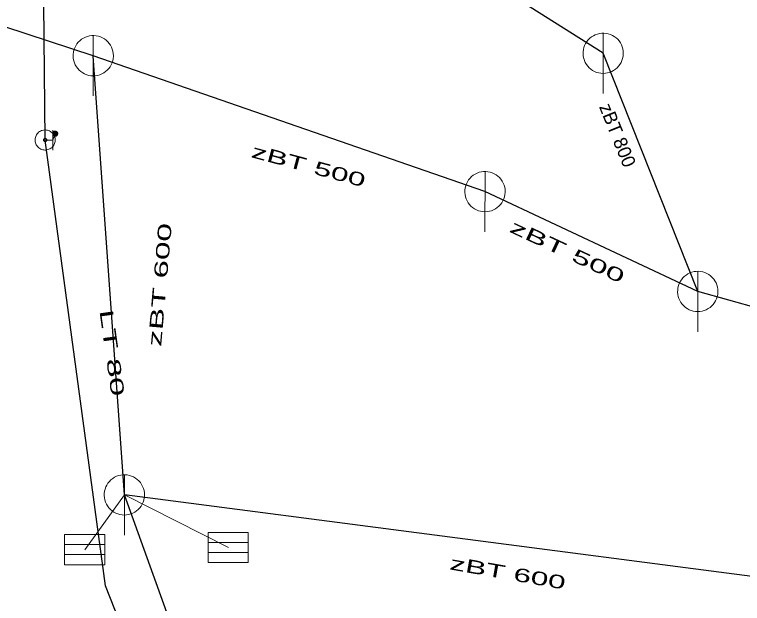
# Model space of a CAD drawing. Extents: x -688432 to -687974, y -973332 to -972704.
# Drawn here: x -688250.99 to -688214.87, y -972905.19 to -972875.96 of the extents above; entities that cross this region are included whole.
import ezdxf
from ezdxf.enums import TextEntityAlignment as Align

# ---------------------------------------------------------------- set-up
doc = ezdxf.new("R2010")
doc.units = 0
doc.header["$LTSCALE"] = 0.27
for name, color, linetype, lineweight in [('1', 7, 'Continuous', 25), ('11', 7, 'Continuous', 13), ('14', 7, 'Continuous', 25), ('17', 7, 'Continuous', 25), ('22', 7, 'Continuous', 13), ('34', 7, 'Continuous', 13), ('47', 7, 'Continuous', 13), ('9', 7, 'Continuous', 13)]:
    doc.layers.add(name, color=color, linetype=linetype, lineweight=lineweight)

msp = doc.modelspace()

# ---------------------------------------------------------------- linework, layer by layer
at = {"layer": '11'}
for p in [(-688247.495, -972902.523), (-688240.377, -972902.418)]:
    msp.add_line(p, (-688245.539, -972899.801), dxfattribs=at)
at = {"layer": '14'}
for p, q in [((-688221.777, -972877.88), (-688271.103, -972846.579)), ((-688217.084, -972889.702), (-688221.777, -972877.88)), ((-688245.539, -972899.801), (-688247.084, -972877.999)), ((-688175.649, -972901.305), (-688217.084, -972889.702)), ((-688238.57, -972919.1), (-688245.539, -972899.801)), ((-688206.6, -972904.874), (-688245.539, -972899.801))]:
    msp.add_line(p, q, dxfattribs=at)
msp.add_lwpolyline([(-688217.084, -972889.702), (-688227.642, -972884.745), (-688247.084, -972877.999), (-688290.938, -972863.596)], dxfattribs=at)
at = {"layer": '14', "lineweight": 13}
msp.add_lwpolyline([(-688249.47, -972882.184), (-688249.091, -972882.189), (-688248.971, -972881.872)], dxfattribs=at)
at = {"layer": '17'}
for points in [[(-688249.47, -972882.184), (-688249.846, -972843.218), (-688249.92, -972842.489), (-688249.989, -972841.809), (-688250.385, -972837.918)], [(-688239.23, -972922.68), (-688246.472, -972904.316), (-688249.47, -972882.184)]]:
    msp.add_lwpolyline(points, dxfattribs=at)
at = {"layer": '22'}
for p, q in [((-688247.084, -972879.999), (-688247.083, -972876.999)), ((-688221.777, -972879.88), (-688221.776, -972876.88)), ((-688227.642, -972886.746), (-688227.641, -972883.746)), ((-688217.084, -972891.702), (-688217.083, -972888.702)), ((-688245.539, -972901.801), (-688245.538, -972898.801)), ((-688248.506, -972902.266), (-688246.506, -972902.266)), ((-688241.388, -972902.161), (-688239.388, -972902.161)), ((-688248.506, -972902.766), (-688246.506, -972902.766)), ((-688241.388, -972902.661), (-688239.388, -972902.661))]:
    msp.add_line(p, q, dxfattribs=at)
for points in [[(-688246.084, -972877.999), (-688246.089, -972877.89), (-688246.107, -972877.782), (-688246.137, -972877.676), (-688246.177, -972877.575), (-688246.229, -972877.478), (-688246.291, -972877.388), (-688246.363, -972877.305), (-688246.443, -972877.231), (-688246.531, -972877.165), (-688246.625, -972877.11), (-688246.725, -972877.065), (-688246.83, -972877.032), (-688246.937, -972877.01), (-688247.046, -972877), (-688247.156, -972877.002), (-688247.264, -972877.016), (-688247.371, -972877.041), (-688247.474, -972877.078), (-688247.572, -972877.127), (-688247.664, -972877.185), (-688247.75, -972877.254), (-688247.827, -972877.331), (-688247.896, -972877.417), (-688247.955, -972877.509), (-688248.003, -972877.607), (-688248.04, -972877.71), (-688248.066, -972877.817), (-688248.08, -972877.925), (-688248.083, -972878.035), (-688248.073, -972878.144), (-688248.052, -972878.251), (-688248.018, -972878.355), (-688247.974, -972878.455), (-688247.919, -972878.55), (-688247.853, -972878.638), (-688247.779, -972878.718), (-688247.696, -972878.79), (-688247.606, -972878.852), (-688247.51, -972878.904), (-688247.408, -972878.945), (-688247.303, -972878.975), (-688247.195, -972878.993), (-688247.085, -972878.999), (-688246.976, -972878.993), (-688246.868, -972878.975), (-688246.763, -972878.946), (-688246.661, -972878.905), (-688246.564, -972878.853), (-688246.474, -972878.791), (-688246.391, -972878.72), (-688246.316, -972878.64), (-688246.251, -972878.552), (-688246.195, -972878.458), (-688246.151, -972878.358), (-688246.117, -972878.254), (-688246.095, -972878.146), (-688246.085, -972878.037)], [(-688220.777, -972877.88), (-688220.782, -972877.771), (-688220.8, -972877.663), (-688220.83, -972877.557), (-688220.87, -972877.456), (-688220.922, -972877.359), (-688220.984, -972877.269), (-688221.056, -972877.186), (-688221.136, -972877.112), (-688221.224, -972877.046), (-688221.318, -972876.991), (-688221.418, -972876.946), (-688221.523, -972876.913), (-688221.63, -972876.891), (-688221.739, -972876.881), (-688221.849, -972876.883), (-688221.957, -972876.897), (-688222.064, -972876.922), (-688222.167, -972876.959), (-688222.265, -972877.008), (-688222.357, -972877.066), (-688222.443, -972877.135), (-688222.52, -972877.212), (-688222.589, -972877.298), (-688222.648, -972877.39), (-688222.696, -972877.488), (-688222.733, -972877.591), (-688222.759, -972877.698), (-688222.773, -972877.806), (-688222.776, -972877.916), (-688222.766, -972878.025), (-688222.745, -972878.132), (-688222.711, -972878.236), (-688222.667, -972878.336), (-688222.612, -972878.431), (-688222.546, -972878.519), (-688222.472, -972878.599), (-688222.389, -972878.671), (-688222.299, -972878.733), (-688222.203, -972878.785), (-688222.101, -972878.826), (-688221.996, -972878.856), (-688221.888, -972878.874), (-688221.778, -972878.88), (-688221.669, -972878.874), (-688221.561, -972878.856), (-688221.456, -972878.827), (-688221.354, -972878.786), (-688221.257, -972878.734), (-688221.167, -972878.672), (-688221.084, -972878.601), (-688221.009, -972878.521), (-688220.944, -972878.433), (-688220.888, -972878.339), (-688220.844, -972878.239), (-688220.81, -972878.135), (-688220.788, -972878.027), (-688220.778, -972877.918)], [(-688226.642, -972884.746), (-688226.647, -972884.637), (-688226.665, -972884.529), (-688226.695, -972884.423), (-688226.735, -972884.322), (-688226.787, -972884.225), (-688226.849, -972884.135), (-688226.921, -972884.052), (-688227.001, -972883.978), (-688227.089, -972883.912), (-688227.183, -972883.857), (-688227.283, -972883.812), (-688227.388, -972883.779), (-688227.495, -972883.757), (-688227.604, -972883.747), (-688227.714, -972883.749), (-688227.822, -972883.763), (-688227.929, -972883.788), (-688228.032, -972883.825), (-688228.13, -972883.874), (-688228.222, -972883.932), (-688228.308, -972884.001), (-688228.385, -972884.078), (-688228.454, -972884.164), (-688228.513, -972884.256), (-688228.561, -972884.354), (-688228.598, -972884.457), (-688228.624, -972884.564), (-688228.638, -972884.672), (-688228.641, -972884.782), (-688228.631, -972884.891), (-688228.61, -972884.998), (-688228.576, -972885.102), (-688228.532, -972885.202), (-688228.477, -972885.297), (-688228.411, -972885.385), (-688228.337, -972885.465), (-688228.254, -972885.537), (-688228.164, -972885.599), (-688228.068, -972885.651), (-688227.966, -972885.692), (-688227.861, -972885.722), (-688227.753, -972885.74), (-688227.643, -972885.746), (-688227.534, -972885.74), (-688227.426, -972885.722), (-688227.321, -972885.693), (-688227.219, -972885.652), (-688227.122, -972885.6), (-688227.032, -972885.538), (-688226.949, -972885.467), (-688226.874, -972885.387), (-688226.809, -972885.299), (-688226.753, -972885.205), (-688226.709, -972885.105), (-688226.675, -972885.001), (-688226.653, -972884.893), (-688226.643, -972884.784)], [(-688216.084, -972889.702), (-688216.089, -972889.593), (-688216.107, -972889.485), (-688216.137, -972889.379), (-688216.177, -972889.278), (-688216.229, -972889.181), (-688216.291, -972889.091), (-688216.363, -972889.008), (-688216.443, -972888.934), (-688216.531, -972888.868), (-688216.625, -972888.813), (-688216.725, -972888.768), (-688216.83, -972888.735), (-688216.937, -972888.713), (-688217.046, -972888.703), (-688217.156, -972888.705), (-688217.264, -972888.719), (-688217.371, -972888.744), (-688217.474, -972888.781), (-688217.572, -972888.83), (-688217.664, -972888.888), (-688217.75, -972888.957), (-688217.827, -972889.034), (-688217.896, -972889.12), (-688217.955, -972889.212), (-688218.003, -972889.31), (-688218.04, -972889.413), (-688218.066, -972889.52), (-688218.08, -972889.628), (-688218.083, -972889.738), (-688218.073, -972889.847), (-688218.052, -972889.954), (-688218.018, -972890.058), (-688217.974, -972890.158), (-688217.919, -972890.253), (-688217.853, -972890.341), (-688217.779, -972890.421), (-688217.696, -972890.493), (-688217.606, -972890.555), (-688217.51, -972890.607), (-688217.408, -972890.648), (-688217.303, -972890.678), (-688217.195, -972890.696), (-688217.085, -972890.702), (-688216.976, -972890.696), (-688216.868, -972890.678), (-688216.763, -972890.649), (-688216.661, -972890.608), (-688216.564, -972890.556), (-688216.474, -972890.494), (-688216.391, -972890.423), (-688216.316, -972890.343), (-688216.251, -972890.255), (-688216.195, -972890.161), (-688216.151, -972890.061), (-688216.117, -972889.957), (-688216.095, -972889.849), (-688216.085, -972889.74)], [(-688244.539, -972899.801), (-688244.544, -972899.692), (-688244.562, -972899.584), (-688244.592, -972899.478), (-688244.632, -972899.377), (-688244.684, -972899.28), (-688244.746, -972899.19), (-688244.818, -972899.107), (-688244.898, -972899.033), (-688244.986, -972898.967), (-688245.08, -972898.912), (-688245.18, -972898.867), (-688245.285, -972898.834), (-688245.392, -972898.812), (-688245.501, -972898.802), (-688245.611, -972898.804), (-688245.719, -972898.818), (-688245.826, -972898.843), (-688245.929, -972898.88), (-688246.027, -972898.929), (-688246.119, -972898.987), (-688246.205, -972899.056), (-688246.282, -972899.133), (-688246.351, -972899.219), (-688246.41, -972899.311), (-688246.458, -972899.409), (-688246.495, -972899.512), (-688246.521, -972899.619), (-688246.535, -972899.727), (-688246.538, -972899.837), (-688246.528, -972899.946), (-688246.507, -972900.053), (-688246.473, -972900.157), (-688246.429, -972900.257), (-688246.374, -972900.352), (-688246.308, -972900.44), (-688246.234, -972900.52), (-688246.151, -972900.592), (-688246.061, -972900.654), (-688245.965, -972900.706), (-688245.863, -972900.747), (-688245.758, -972900.777), (-688245.65, -972900.795), (-688245.54, -972900.801), (-688245.431, -972900.795), (-688245.323, -972900.777), (-688245.218, -972900.748), (-688245.116, -972900.707), (-688245.019, -972900.655), (-688244.929, -972900.593), (-688244.846, -972900.522), (-688244.771, -972900.442), (-688244.706, -972900.354), (-688244.65, -972900.26), (-688244.606, -972900.16), (-688244.572, -972900.056), (-688244.55, -972899.948), (-688244.54, -972899.839)], [(-688248.506, -972901.766), (-688246.506, -972901.766), (-688246.506, -972903.266), (-688248.506, -972903.266)], [(-688241.388, -972901.661), (-688239.388, -972901.661), (-688239.388, -972903.161), (-688241.388, -972903.161)]]:
    msp.add_lwpolyline(points, close=True, dxfattribs=at)
at = {"layer": '34'}
msp.add_line((-688249.091, -972881.689), (-688249.091, -972882.689), dxfattribs=at)
at = {"layer": '47'}
for points in [[(-688249.432, -972882.682), (-688249.381, -972882.675), (-688249.329, -972882.663), (-688249.281, -972882.646), (-688249.233, -972882.624), (-688249.188, -972882.597), (-688249.146, -972882.565), (-688249.109, -972882.529), (-688249.075, -972882.489), (-688249.045, -972882.447), (-688249.019, -972882.401), (-688248.999, -972882.352), (-688248.984, -972882.302), (-688248.974, -972882.251), (-688248.97, -972882.198), (-688248.971, -972882.146), (-688248.978, -972882.095), (-688248.99, -972882.043), (-688249.007, -972881.994), (-688249.029, -972881.947), (-688249.056, -972881.902), (-688249.088, -972881.86), (-688249.124, -972881.822), (-688249.164, -972881.788), (-688249.206, -972881.758), (-688249.252, -972881.733), (-688249.301, -972881.713), (-688249.351, -972881.697), (-688249.402, -972881.688), (-688249.455, -972881.684), (-688249.507, -972881.685), (-688249.558, -972881.692), (-688249.61, -972881.704), (-688249.659, -972881.72), (-688249.706, -972881.743), (-688249.751, -972881.77), (-688249.793, -972881.801), (-688249.831, -972881.837), (-688249.865, -972881.877), (-688249.895, -972881.92), (-688249.92, -972881.966), (-688249.94, -972882.015), (-688249.956, -972882.064), (-688249.965, -972882.116), (-688249.969, -972882.169), (-688249.968, -972882.221), (-688249.961, -972882.272), (-688249.949, -972882.324), (-688249.933, -972882.372), (-688249.91, -972882.42), (-688249.883, -972882.465), (-688249.852, -972882.507), (-688249.816, -972882.544), (-688249.776, -972882.578), (-688249.733, -972882.608), (-688249.687, -972882.634), (-688249.638, -972882.654), (-688249.589, -972882.669), (-688249.537, -972882.679), (-688249.484, -972882.683)], [(-688249.463, -972882.265), (-688249.454, -972882.265), (-688249.447, -972882.262), (-688249.439, -972882.259), (-688249.431, -972882.256), (-688249.423, -972882.251), (-688249.417, -972882.246), (-688249.41, -972882.24), (-688249.405, -972882.234), (-688249.4, -972882.226), (-688249.396, -972882.219), (-688249.392, -972882.211), (-688249.39, -972882.203), (-688249.388, -972882.195), (-688249.387, -972882.186), (-688249.388, -972882.177), (-688249.388, -972882.168), (-688249.391, -972882.161), (-688249.394, -972882.153), (-688249.397, -972882.145), (-688249.402, -972882.137), (-688249.407, -972882.131), (-688249.413, -972882.124), (-688249.419, -972882.119), (-688249.427, -972882.113), (-688249.434, -972882.11), (-688249.442, -972882.106), (-688249.45, -972882.104), (-688249.458, -972882.102), (-688249.467, -972882.101), (-688249.476, -972882.102), (-688249.485, -972882.102), (-688249.492, -972882.105), (-688249.5, -972882.108), (-688249.508, -972882.111), (-688249.516, -972882.116), (-688249.522, -972882.12), (-688249.529, -972882.127), (-688249.534, -972882.133), (-688249.54, -972882.141), (-688249.543, -972882.148), (-688249.547, -972882.156), (-688249.549, -972882.164), (-688249.551, -972882.172), (-688249.552, -972882.181), (-688249.551, -972882.19), (-688249.551, -972882.199), (-688249.548, -972882.206), (-688249.545, -972882.214), (-688249.542, -972882.222), (-688249.537, -972882.23), (-688249.533, -972882.236), (-688249.526, -972882.243), (-688249.52, -972882.248), (-688249.512, -972882.253), (-688249.505, -972882.257), (-688249.497, -972882.261), (-688249.489, -972882.263), (-688249.481, -972882.265), (-688249.472, -972882.266)]]:
    msp.add_lwpolyline(points, close=True, dxfattribs=at)
at = {"layer": '9'}
for points in [[(-688249.097, -972881.872), (-688249.097, -972881.885), (-688249.095, -972881.898), (-688249.092, -972881.911), (-688249.087, -972881.923), (-688249.081, -972881.935), (-688249.074, -972881.946), (-688249.066, -972881.956), (-688249.056, -972881.966), (-688249.046, -972881.974), (-688249.035, -972881.981), (-688249.023, -972881.987), (-688249.011, -972881.992), (-688248.998, -972881.995), (-688248.985, -972881.997), (-688248.972, -972881.999), (-688248.959, -972881.998), (-688248.946, -972881.996), (-688248.933, -972881.993), (-688248.921, -972881.988), (-688248.909, -972881.982), (-688248.898, -972881.975), (-688248.888, -972881.967), (-688248.878, -972881.957), (-688248.87, -972881.947), (-688248.863, -972881.936), (-688248.857, -972881.924), (-688248.852, -972881.912), (-688248.849, -972881.899), (-688248.847, -972881.886), (-688248.845, -972881.873), (-688248.846, -972881.86), (-688248.848, -972881.847), (-688248.851, -972881.834), (-688248.856, -972881.822), (-688248.862, -972881.81), (-688248.869, -972881.799), (-688248.877, -972881.789), (-688248.887, -972881.779), (-688248.897, -972881.771), (-688248.908, -972881.764), (-688248.92, -972881.758), (-688248.932, -972881.753), (-688248.945, -972881.75), (-688248.958, -972881.748), (-688248.971, -972881.747), (-688248.984, -972881.747), (-688248.997, -972881.749), (-688249.01, -972881.752), (-688249.022, -972881.757), (-688249.034, -972881.763), (-688249.045, -972881.77), (-688249.055, -972881.778), (-688249.065, -972881.788), (-688249.073, -972881.798), (-688249.08, -972881.809), (-688249.086, -972881.821), (-688249.091, -972881.833), (-688249.094, -972881.846), (-688249.096, -972881.859)], [(-688249.077, -972881.872), (-688249.078, -972881.883), (-688249.076, -972881.894), (-688249.073, -972881.905), (-688249.069, -972881.915), (-688249.064, -972881.925), (-688249.058, -972881.934), (-688249.051, -972881.943), (-688249.043, -972881.951), (-688249.034, -972881.958), (-688249.025, -972881.964), (-688249.015, -972881.969), (-688249.005, -972881.973), (-688248.994, -972881.976), (-688248.983, -972881.979), (-688248.972, -972881.979), (-688248.961, -972881.979), (-688248.95, -972881.977), (-688248.939, -972881.974), (-688248.929, -972881.97), (-688248.919, -972881.965), (-688248.91, -972881.959), (-688248.901, -972881.952), (-688248.893, -972881.944), (-688248.886, -972881.935), (-688248.88, -972881.926), (-688248.875, -972881.916), (-688248.871, -972881.906), (-688248.868, -972881.895), (-688248.866, -972881.884), (-688248.865, -972881.873), (-688248.865, -972881.862), (-688248.867, -972881.851), (-688248.87, -972881.84), (-688248.874, -972881.83), (-688248.879, -972881.82), (-688248.885, -972881.811), (-688248.892, -972881.802), (-688248.9, -972881.794), (-688248.909, -972881.787), (-688248.918, -972881.781), (-688248.928, -972881.776), (-688248.938, -972881.772), (-688248.949, -972881.769), (-688248.96, -972881.767), (-688248.971, -972881.767), (-688248.982, -972881.766), (-688248.993, -972881.768), (-688249.004, -972881.771), (-688249.014, -972881.775), (-688249.024, -972881.78), (-688249.033, -972881.786), (-688249.042, -972881.793), (-688249.05, -972881.801), (-688249.057, -972881.81), (-688249.063, -972881.819), (-688249.068, -972881.829), (-688249.072, -972881.839), (-688249.075, -972881.85), (-688249.077, -972881.861)], [(-688249.058, -972881.872), (-688249.058, -972881.881), (-688249.057, -972881.89), (-688249.054, -972881.899), (-688249.051, -972881.907), (-688249.047, -972881.915), (-688249.042, -972881.923), (-688249.036, -972881.93), (-688249.03, -972881.936), (-688249.023, -972881.942), (-688249.015, -972881.947), (-688249.007, -972881.951), (-688248.999, -972881.954), (-688248.99, -972881.957), (-688248.981, -972881.958), (-688248.972, -972881.96), (-688248.963, -972881.959), (-688248.954, -972881.958), (-688248.945, -972881.955), (-688248.937, -972881.952), (-688248.929, -972881.948), (-688248.921, -972881.943), (-688248.914, -972881.937), (-688248.908, -972881.931), (-688248.902, -972881.924), (-688248.897, -972881.916), (-688248.893, -972881.908), (-688248.89, -972881.9), (-688248.887, -972881.891), (-688248.886, -972881.882), (-688248.884, -972881.873), (-688248.885, -972881.864), (-688248.886, -972881.855), (-688248.889, -972881.846), (-688248.892, -972881.838), (-688248.896, -972881.83), (-688248.901, -972881.822), (-688248.907, -972881.815), (-688248.913, -972881.809), (-688248.92, -972881.803), (-688248.928, -972881.798), (-688248.936, -972881.794), (-688248.944, -972881.791), (-688248.953, -972881.788), (-688248.962, -972881.787), (-688248.971, -972881.786), (-688248.98, -972881.786), (-688248.989, -972881.787), (-688248.998, -972881.79), (-688249.006, -972881.793), (-688249.014, -972881.797), (-688249.022, -972881.802), (-688249.029, -972881.808), (-688249.035, -972881.814), (-688249.041, -972881.821), (-688249.046, -972881.829), (-688249.05, -972881.837), (-688249.053, -972881.845), (-688249.056, -972881.854), (-688249.057, -972881.863)], [(-688249.038, -972881.872), (-688249.038, -972881.879), (-688249.037, -972881.886), (-688249.036, -972881.893), (-688249.033, -972881.899), (-688249.03, -972881.905), (-688249.026, -972881.911), (-688249.022, -972881.917), (-688249.017, -972881.922), (-688249.011, -972881.926), (-688249.005, -972881.93), (-688248.999, -972881.933), (-688248.993, -972881.936), (-688248.986, -972881.937), (-688248.979, -972881.94), (-688248.972, -972881.94), (-688248.965, -972881.94), (-688248.958, -972881.938), (-688248.951, -972881.937), (-688248.945, -972881.934), (-688248.938, -972881.931), (-688248.933, -972881.927), (-688248.927, -972881.923), (-688248.922, -972881.918), (-688248.918, -972881.912), (-688248.914, -972881.906), (-688248.911, -972881.9), (-688248.908, -972881.894), (-688248.906, -972881.887), (-688248.905, -972881.88), (-688248.904, -972881.873), (-688248.904, -972881.866), (-688248.905, -972881.859), (-688248.907, -972881.852), (-688248.91, -972881.846), (-688248.913, -972881.839), (-688248.917, -972881.834), (-688248.921, -972881.828), (-688248.926, -972881.823), (-688248.932, -972881.819), (-688248.937, -972881.815), (-688248.944, -972881.812), (-688248.95, -972881.809), (-688248.957, -972881.807), (-688248.964, -972881.806), (-688248.971, -972881.806), (-688248.978, -972881.806), (-688248.985, -972881.806), (-688248.992, -972881.808), (-688248.998, -972881.811), (-688249.004, -972881.814), (-688249.01, -972881.818), (-688249.016, -972881.822), (-688249.021, -972881.827), (-688249.025, -972881.833), (-688249.029, -972881.838), (-688249.032, -972881.845), (-688249.035, -972881.851), (-688249.036, -972881.858), (-688249.038, -972881.865)], [(-688249.018, -972881.872), (-688249.018, -972881.877), (-688249.018, -972881.882), (-688249.017, -972881.887), (-688249.015, -972881.891), (-688249.013, -972881.896), (-688249.01, -972881.9), (-688249.007, -972881.903), (-688249.003, -972881.907), (-688249, -972881.91), (-688248.996, -972881.913), (-688248.991, -972881.915), (-688248.987, -972881.917), (-688248.982, -972881.918), (-688248.977, -972881.92), (-688248.972, -972881.92), (-688248.967, -972881.92), (-688248.962, -972881.919), (-688248.957, -972881.918), (-688248.953, -972881.916), (-688248.948, -972881.914), (-688248.944, -972881.911), (-688248.94, -972881.908), (-688248.937, -972881.904), (-688248.934, -972881.901), (-688248.931, -972881.897), (-688248.929, -972881.892), (-688248.927, -972881.888), (-688248.926, -972881.883), (-688248.925, -972881.878), (-688248.924, -972881.873), (-688248.924, -972881.868), (-688248.925, -972881.863), (-688248.926, -972881.858), (-688248.928, -972881.854), (-688248.93, -972881.849), (-688248.933, -972881.845), (-688248.936, -972881.841), (-688248.939, -972881.838), (-688248.943, -972881.835), (-688248.947, -972881.832), (-688248.952, -972881.83), (-688248.956, -972881.828), (-688248.961, -972881.827), (-688248.966, -972881.826), (-688248.971, -972881.826), (-688248.976, -972881.826), (-688248.981, -972881.827), (-688248.986, -972881.827), (-688248.99, -972881.829), (-688248.995, -972881.831), (-688248.999, -972881.834), (-688249.002, -972881.837), (-688249.006, -972881.84), (-688249.009, -972881.844), (-688249.012, -972881.848), (-688249.014, -972881.853), (-688249.016, -972881.857), (-688249.017, -972881.862), (-688249.018, -972881.867)], [(-688248.998, -972881.872), (-688248.998, -972881.875), (-688248.999, -972881.878), (-688248.998, -972881.88), (-688248.997, -972881.883), (-688248.996, -972881.886), (-688248.994, -972881.888), (-688248.992, -972881.89), (-688248.99, -972881.892), (-688248.988, -972881.894), (-688248.986, -972881.896), (-688248.983, -972881.898), (-688248.98, -972881.899), (-688248.978, -972881.899), (-688248.975, -972881.9), (-688248.972, -972881.9), (-688248.969, -972881.9), (-688248.966, -972881.9), (-688248.963, -972881.899), (-688248.961, -972881.898), (-688248.958, -972881.897), (-688248.956, -972881.895), (-688248.953, -972881.893), (-688248.951, -972881.891), (-688248.95, -972881.889), (-688248.948, -972881.887), (-688248.947, -972881.884), (-688248.945, -972881.881), (-688248.945, -972881.879), (-688248.944, -972881.876), (-688248.943, -972881.873), (-688248.944, -972881.87), (-688248.944, -972881.867), (-688248.945, -972881.864), (-688248.946, -972881.862), (-688248.947, -972881.859), (-688248.949, -972881.857), (-688248.95, -972881.854), (-688248.952, -972881.852), (-688248.955, -972881.851), (-688248.957, -972881.849), (-688248.96, -972881.848), (-688248.962, -972881.847), (-688248.965, -972881.846), (-688248.968, -972881.846), (-688248.971, -972881.845), (-688248.974, -972881.846), (-688248.977, -972881.845), (-688248.979, -972881.847), (-688248.982, -972881.847), (-688248.985, -972881.848), (-688248.987, -972881.85), (-688248.989, -972881.851), (-688248.991, -972881.853), (-688248.993, -972881.856), (-688248.995, -972881.858), (-688248.996, -972881.861), (-688248.997, -972881.863), (-688248.998, -972881.866), (-688248.998, -972881.869)], [(-688248.979, -972881.872), (-688248.979, -972881.874), (-688248.979, -972881.874), (-688248.978, -972881.874), (-688248.978, -972881.876), (-688248.979, -972881.877), (-688248.977, -972881.877), (-688248.977, -972881.877), (-688248.977, -972881.879), (-688248.977, -972881.879), (-688248.976, -972881.88), (-688248.974, -972881.88), (-688248.974, -972881.88), (-688248.974, -972881.881), (-688248.972, -972881.881), (-688248.972, -972881.881), (-688248.971, -972881.881), (-688248.97, -972881.881), (-688248.97, -972881.88), (-688248.969, -972881.88), (-688248.967, -972881.88), (-688248.967, -972881.879), (-688248.967, -972881.879), (-688248.966, -972881.878), (-688248.966, -972881.878), (-688248.964, -972881.877), (-688248.964, -972881.876), (-688248.963, -972881.875), (-688248.963, -972881.875), (-688248.963, -972881.874), (-688248.963, -972881.873), (-688248.963, -972881.872), (-688248.963, -972881.871), (-688248.963, -972881.871), (-688248.964, -972881.87), (-688248.964, -972881.869), (-688248.965, -972881.868), (-688248.965, -972881.868), (-688248.966, -972881.867), (-688248.966, -972881.867), (-688248.967, -972881.866), (-688248.968, -972881.866), (-688248.969, -972881.865), (-688248.969, -972881.865), (-688248.97, -972881.865), (-688248.971, -972881.865), (-688248.972, -972881.865), (-688248.973, -972881.865), (-688248.973, -972881.865), (-688248.974, -972881.866), (-688248.975, -972881.865), (-688248.976, -972881.867), (-688248.976, -972881.867), (-688248.977, -972881.867), (-688248.977, -972881.867), (-688248.978, -972881.869), (-688248.978, -972881.87), (-688248.978, -972881.871), (-688248.979, -972881.871), (-688248.979, -972881.872)]]:
    msp.add_lwpolyline(points, close=True, dxfattribs=at)

# ---------------------------------------------------------------- texts
at = {"layer": '1'}
msp.add_text('zBT 800 ', height=0.6667, rotation=292, dxfattribs=at).set_placement((-688221.3233, -972882.1825), align=Align.CENTER)
msp.add_text('zBT 800 ', height=0.6667, rotation=292, dxfattribs=at).set_placement((-688221.3233, -972882.1825), align=Align.CENTER)
msp.add_text('zBT 800 ', height=0.6667, rotation=292, dxfattribs=at).set_placement((-688221.3233, -972882.1825), align=Align.CENTER)
msp.add_text('zBT 800 ', height=0.6667, rotation=292, dxfattribs=at).set_placement((-688221.3233, -972882.1825), align=Align.CENTER)
msp.add_text('zBT 800 ', height=0.6667, rotation=292, dxfattribs=at).set_placement((-688221.3233, -972882.1825), align=Align.CENTER)
for s, rotation, width, p in [('zBT 500 ', 345, 1.75, (-688236.2723, -972883.8371)), ('zBT 500 ', 345, 1.75, (-688236.2723, -972883.8371)), ('zBT 500 ', 345, 1.75, (-688236.2723, -972883.8371)), ('zBT 500 ', 345, 1.75, (-688236.2723, -972883.8371)), ('zBT 500 ', 345, 1.75, (-688236.2723, -972883.8371)), ('zBT 600 ', 85, 1.85, (-688243.4283, -972889.1721)), ('zBT 600 ', 85, 1.85, (-688243.4283, -972889.1721)), ('zBT 600 ', 85, 1.85, (-688243.4283, -972889.1721)), ('zBT 600 ', 85, 1.85, (-688243.4283, -972889.1721)), ('zBT 600 ', 85, 1.85, (-688243.4283, -972889.1721)), ('zBT 500 ', 335, 1.85, (-688223.4859, -972888.118)), ('zBT 500 ', 335, 1.85, (-688223.4859, -972888.118)), ('zBT 500 ', 335, 1.85, (-688223.4859, -972888.118)), ('zBT 500 ', 335, 1.85, (-688223.4859, -972888.118)), ('zBT 500 ', 335, 1.85, (-688223.4859, -972888.118)), ('LT 80 ', 278, 1.9, (-688246.4447, -972893.0286)), ('LT 80 ', 278, 1.9, (-688246.4447, -972893.0286)), ('LT 80 ', 278, 1.9, (-688246.4447, -972893.0286)), ('LT 80 ', 278, 1.9, (-688246.4447, -972893.0286)), ('LT 80 ', 278, 1.9, (-688246.4447, -972893.0286)), ('zBT 600 ', 350, 1.75, (-688226.3539, -972904.0369)), ('zBT 600 ', 350, 1.75, (-688226.3539, -972904.0369)), ('zBT 600 ', 350, 1.75, (-688226.3539, -972904.0369)), ('zBT 600 ', 350, 1.75, (-688226.3539, -972904.0369)), ('zBT 600 ', 350, 1.75, (-688226.3539, -972904.0369))]:
    msp.add_text(s, height=0.6667, rotation=rotation, dxfattribs=dict(at, width=width)).set_placement(p, align=Align.CENTER)

doc.saveas('drawing.dxf')
